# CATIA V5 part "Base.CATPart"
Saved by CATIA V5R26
Part number: Part1
Bounding box of the stored display mesh (mm): x -50 to 50, y -25 to 25, z 0 to 50
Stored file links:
  D:\_Deepak\CATIA\CATIA V5-6R2016_Deepak\Resources\Part files\Partfiles\c12_catia_v5_6r2016_prt\c12_catia_v5-6r2016 figr_12-12\Base.CATPart
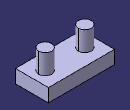
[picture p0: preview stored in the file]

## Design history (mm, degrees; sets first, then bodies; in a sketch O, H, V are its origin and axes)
Body1 (main body)
  Sketch1 on xy-plane, origin (0, 0, 0), H (1, 0, 0), V (0, 1, 0)
    line L1 (50, 25) -> (50, -25)
    line L2 (50, -25) -> (-50, -25)
    line L3 (-50, -25) -> (-50, 25)
    line L4 (-50, 25) -> (50, 25)
    circle A1 centre (-30, 0) radius 10
    point P5 (-30, 0)
    circle A2 centre (30, 0) radius 10
    length L2 = 100
    length L1 = 50
    radius A1 = 10
    distance P5 V = 30
    vertical: L1 V, L3 V
    horizontal: L2 H, L4 H
    equidistance: L1 L3 O, L2 L4 O
    coincidence: P5 H
    symmetry: A1 A2 V
  MultiPad1: profile Sketch1, domains (length 20; length 50; length 50)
